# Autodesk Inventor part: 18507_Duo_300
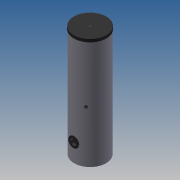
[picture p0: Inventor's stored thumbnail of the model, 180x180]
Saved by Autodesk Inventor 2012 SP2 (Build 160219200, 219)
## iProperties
allow_slope_adjustment: 0 ul
connection_type: 13 ul
flow_configuration2: 1 ul
flow_direction: 2 ul
loss_method: 0 ul
radius: 15,375 mm
radius: 22,625 mm
radius: 19,625 mm
description: 0:0:18506_Duo_300
manufacturer: 0:0:Flamco Group
model: 0:0:Duo 300
url: 0:0:www.flamcogroup.com
radius: 9,500 mm
Created: 2014-05
Part Number: 18507_Duo_300
Material: Default
Document SubType Name: Modeling
Designer: michel
Density: 1 g/cm^3
Author: michel
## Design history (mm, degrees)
sketch "Sketch1"
  geometry: C1 r 280 at (0, 0); 1 further point
  constraints: 1 centre point, 1 coincident
  dimensions: "d0" = 560 diameter of C1
extrude "Extrusion1" new body sketch "Sketch1" distance "d1" = 1950; taper "d2" = 0 deg
sketch "Sketch2"
  geometry: L1 (-280, 1950)-(280, 1950) reference; L2 (280, 0)-(280, 1950) reference; L3 (280, 1950)-(280, 1900); L4 (285, 1900)-(285, 1950); L5 (285, 1950)-(280, 1950); L6 (0, -290)-(0, 1740) reference; L7 (285, 1900)-(280, 1900); 1 further point
  constraints: 8 end point, 1 parallel
revolve "Revolution1" sketch "Sketch2" stored, may be unused: angle "d6" = 90 deg
workplane "Work Plane1"
workplane "Work Plane2"
workplane "Work Plane3"
workplane "Work Plane4"
workplane "Work Plane5"
workplane "Work Plane6"
sketch "Sketch3"
  geometry: L1 (404, 1785)-(-394, 1785) reference; L2 (404, 910)-(-394, 910) reference; L3 (404, 1035)-(-394, 1035) reference; L4 (404, 245)-(-394, 245) reference; L5 (404, 65)-(-394, 65) reference; L6 (280, 0)-(280, 1900) reference; L7 (290, 1785)-(240, 1785); L8 (240, 1785)-(240, 1801.625); L9 (240, 1801.625)-(290, 1801.625); L10 (290, 1801.625)-(290, 1785); L11 (290, 65)-(240, 65); L12 (240, 65)-(240, 81.625); L13 (240, 81.625)-(290, 81.625); L14 (290, 81.625)-(290, 65); L15 (280, 910)-(240, 910); L16 (240, 910)-(240, 920.475); L17 (240, 920.475)-(280, 920.475); L18 (280, 920.475)-(280, 910); L19 (280, 1035)-(240, 1035); L20 (240, 1035)-(240, 1051.625); L21 (240, 1051.625)-(280, 1051.625); L22 (280, 1051.625)-(280, 1035); L23 (240, 261.625)-(280, 261.625); L24 (280, 261.625)-(280, 245); L25 (280, 245)-(240, 245); L26 (240, 245)-(240, 261.625); 1 further point
  constraints: 40 end point, 8 parallel, 4 point on line, 3 horizontal, 3 perpendicular
  dimensions: "d13" = 50 distance of L8.end L9.end; "d14" = 16.625 distance of L7.end L8.end; "d15" = 50 distance of L12.end L13.end; "d16" = 16.625 distance of L11.end L12.end; "d17" = 40 distance of L16.end L17.end; "d18" = 10.475 distance of L15.end L16.end; "d19" = 40 distance of L20.end L21.end; "d20" = 16.625 distance of L19.end L20.end; "d21" = 40 distance of L23.start L23.end; "d22" = 16.625 distance of L25.end L23.start
revolve "Revolution2" stored, may be unused: angle "d23" = 90 deg
revolve "Revolution3" stored, may be unused: angle "d24" = 90 deg
revolve "Revolution4" stored, may be unused: angle "d25" = 90 deg
revolve "Revolution5" stored, may be unused: angle "d26" = 90 deg
revolve "Revolution6" stored, may be unused: angle "d27" = 90 deg
revolve "Revolution7" stored, may be unused: angle "d28" = 90 deg
revolve "Revolution8" stored, may be unused: angle "d29" = 90 deg
sketch "Sketch4"
  geometry: C1 r 16.625 at (0, 0) reference; C2 r 15.375 at (0, 0); 1 further point
  constraints: 1 centre point, 1 coincident
  dimensions: "d30" = 30.75 diameter of C2
extrude "Extrusion2" cut sketch "Sketch4" distance "d31" = 40; taper "d32" = 0 deg
sketch "Sketch5"
  geometry: C1 r 16.625 at (0, 0) reference; C2 r 15.375 at (0, 0); 1 further point
  constraints: 1 centre point, 1 coincident
  dimensions: "d33" = 30.75 diameter of C2
extrude "Extrusion3" cut sketch "Sketch5" distance "d34" = 40; taper "d35" = 0 deg
workplane "Work Plane7"
sketch "Sketch6"
  geometry: C1 r 9.5 at (0, 0); C2 r 16.625 at (0, 125) reference; C3 r 16.625 at (0, -665) reference; C4 r 15.375 at (0, 125); C5 r 15.375 at (0, -665); 7 further points
  constraints: 6 vertical alignment, 3 centre point, 2 coincident
  dimensions: "d36" = 19 diameter of C1; "d37" = 30.75 diameter of C4; "d38" = 30.75 diameter of C5
  node "Projected Loop1"
  node "Projected Loop2"
extrude "Extrusion4" join sketch "Sketch6" distance "d39" = 40; taper "d40" = 0 deg
extrude "Extrusion5" join sketch "Sketch6" distance "d41" = 40; taper "d42" = 0 deg
extrude "Extrusion6" join sketch "Sketch6" distance "d43" = 40; taper "d44" = 0 deg
workplane "Work Plane8"
workplane "Work Plane9"
sketch "Sketch7"
  geometry: L1 (394.5, 327)-(-407, 327) reference; L2 (-280, 0)-(-280, 1900) reference; L3 (-280, 327)-(-292.5, 327); L4 (-292.5, 327)-(-292.5, 417); L5 (-292.5, 417)-(-280, 417); L6 (-280, 417)-(-280, 327); 1 further point
  constraints: 8 end point, 2 parallel, 2 point on line, 1 horizontal, 1 perpendicular
  dimensions: "d47" = 12.5 distance of L4.end L5.end; "d48" = 90 distance of L3.end L4.end
revolve "Revolution9" sketch "Sketch7" stored, may be unused: angle "d49" = 90 deg
sketch "Sketch8"
  geometry: C1 r 62.5 at (0, 0); A1 r 90 centre (0, 0) between (0, -90) and (0, 90) reference; 1 further point
  constraints: 1 centre point, 1 coincident
  dimensions: "d50" = 125 diameter of C1
extrude "Extrusion7" join sketch "Sketch8" stored distance "d51" = 10; taper "d52" = 0 deg
sketch "Sketch9"
  geometry: C1 r 90 at (0, 0) reference; C2 r 55 at (0, 0); 1 further point
  constraints: 1 centre point, 1 coincident
  dimensions: "d53" = 110 diameter of C2
extrude "Extrusion8" cut sketch "Sketch9" distance "d54" = 50; taper "d55" = 0 deg
sketch "Sketch10"
  geometry: C1 r 285 at (0, 0) reference; C2 r 20.955 at (0, 0); C3 r 19.625 at (0, 0)
  constraints: 2 centre point, 2 coincident
  dimensions: "d56" = 41.91 diameter of C2; "d59" = 39.25 diameter of C3
extrude "Extrusion9" cut sketch "Sketch10" distance "d57" = 50; taper "d58" = 0 deg
extrude "Extrusion10" join sketch "Sketch10" distance "d60" = 50; taper "d61" = 0 deg
workplane "Work Plane10"
sketch "Sketch11"
  geometry: L1 (910, -545.95)-(910, 545.95) reference; L2 (0, 280)-(1900, 280) reference; L3 (910, 280)-(933.9, 280); L4 (933.9, 280)-(933.9, 240); L5 (933.9, 240)-(910, 240); L6 (910, 240)-(910, 280); L7 (887.375, 240)-(887.375, 280); L8 (887.375, 240)-(884.825, 240); L9 (884.825, 240)-(884.825, 280); L10 (887.375, 280)-(884.825, 280); 1 further point
  constraints: 16 end point, 4 perpendicular, 4 point on line, 2 parallel, 1 horizontal
  dimensions: "d63" = 23.9 distance of L4.end L5.end; "d64" = 40 distance of L3.end L4.end; "d67" = 22.625 distance of L5.end L7.start; "d68" = 2.55 distance of L7.start L8.end
revolve "Revolution10" stored, may be unused: angle "d65" = 90 deg
revolve "Revolution11" stored, may be unused: angle "d69" = 90 deg
body "Solid1"
other parameters: "d8" = -65, "d9" = -245, "d12" = 0, "d45" = -327, "d46" = 0, "d62" = 35 deg, "d76" = -1785, "d77" = -1035
